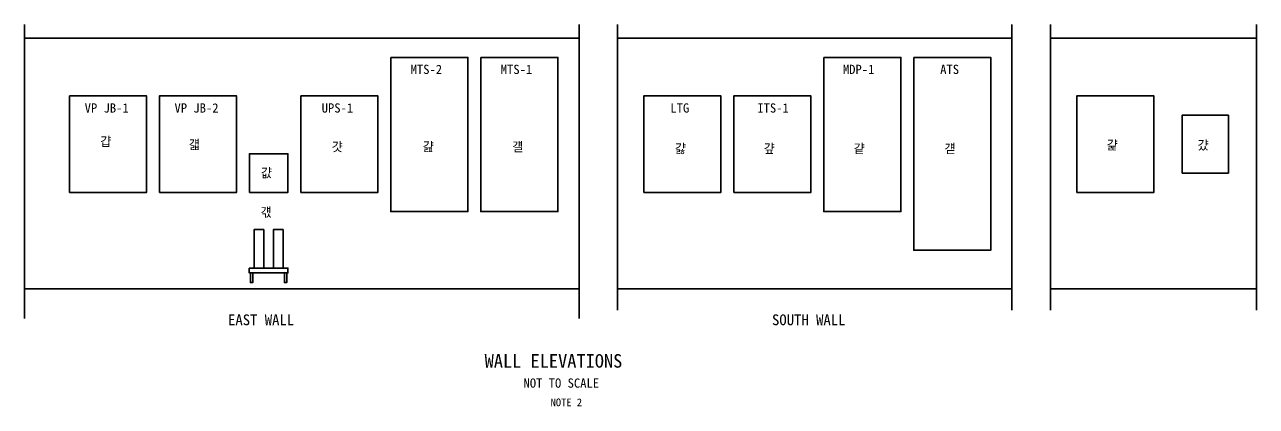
# Model space of a CAD drawing. Extents: x 0 to 31.9, y -2.3 to 7.6.
import ezdxf

# ---------------------------------------------------------------- set-up
doc = ezdxf.new("R2010")
doc.units = 0
doc.layers.add('Sheets_General Details - Sheet Number Text', color=7, linetype='Continuous')
doc.layers.add('Sheets_General Details - Version Text', color=7, linetype='Continuous')

msp = doc.modelspace()

# ---------------------------------------------------------------- linework, layer by layer
at = {"layer": 'Sheets_General Details - Version Text'}
for p, q in [((0, 7.617), (0, 0)), ((14.379, 7.617), (14.379, 0)), ((15.379, 7.617), (15.379, 0.214)), ((25.608, 7.617), (25.608, 0.214)), ((26.608, 7.617), (26.608, 0.214)), ((31.947, 7.617), (31.947, 0.214)), ((14.379, 7.269), (0, 7.269)), ((25.608, 7.269), (15.379, 7.269)), ((31.947, 7.269), (26.608, 7.269)), ((14.379, 0.769), (0, 0.769)), ((25.608, 0.769), (15.379, 0.769)), ((31.947, 0.769), (26.608, 0.769))]:
    msp.add_line(p, q, dxfattribs=at)
for points in [[(9.497, 6.769), (11.497, 6.769), (11.497, 2.769), (9.497, 2.769)], [(11.83, 6.769), (13.83, 6.769), (13.83, 2.769), (11.83, 2.769)], [(20.726, 6.769), (22.726, 6.769), (22.726, 2.769), (20.726, 2.769)], [(23.06, 6.769), (25.06, 6.769), (25.06, 1.769), (23.06, 1.769)], [(1.164, 3.269), (3.164, 3.269), (3.164, 5.769), (1.164, 5.769)], [(3.497, 3.269), (5.497, 3.269), (5.497, 5.769), (3.497, 5.769)], [(7.164, 3.269), (9.164, 3.269), (9.164, 5.769), (7.164, 5.769)], [(16.06, 3.269), (18.06, 3.269), (18.06, 5.769), (16.06, 5.769)], [(18.393, 3.269), (20.393, 3.269), (20.393, 5.769), (18.393, 5.769)], [(27.289, 3.269), (29.289, 3.269), (29.289, 5.769), (27.289, 5.769)], [(30.022, 3.769), (31.222, 3.769), (31.222, 5.269), (30.022, 5.269)], [(5.83, 3.269), (6.83, 3.269), (6.83, 4.269), (5.83, 4.269)], [(6.202, 1.306), (5.952, 1.306), (5.952, 2.306), (6.202, 2.306)], [(6.702, 1.306), (6.452, 1.306), (6.452, 2.306), (6.702, 2.306)], [(5.827, 1.306), (6.827, 1.306), (6.827, 1.181), (5.827, 1.181)], [(5.917, 1.181), (5.857, 1.181), (5.857, 0.931), (5.917, 0.931)], [(6.797, 1.181), (6.737, 1.181), (6.737, 0.931), (6.797, 0.931)]]:
    msp.add_lwpolyline(points, close=True, dxfattribs=at)

# ---------------------------------------------------------------- texts
at = {"layer": 'Sheets_General Details - Sheet Number Text'}
for s, height, p in [('MTS-2', 0.24, (10.011, 6.337)), ('MTS-1', 0.24, (12.348, 6.337)), ('MDP-1', 0.24, (21.223, 6.337)), ('ATS', 0.24, (23.746, 6.337)), ('VP JB-1', 0.24, (1.557, 5.337)), ('VP JB-2', 0.24, (3.887, 5.337)), ('UPS-1', 0.24, (7.704, 5.337)), ('LTG', 0.24, (16.748, 5.337)), ('ITS-1', 0.24, (19.003, 5.337)), ('걉', 0.24, (1.963, 4.466)), ('걟', 0.24, (4.257, 4.388)), ('걋', 0.24, (7.966, 4.333)), ('걆', 0.24, (10.328, 4.333)), ('걜', 0.24, (12.646, 4.333)), ('걇', 0.24, (16.868, 4.283)), ('걒', 0.24, (19.169, 4.285)), ('걑', 0.24, (21.501, 4.283)), ('걛', 0.24, (23.856, 4.283)), ('걅', 0.24, (28.069, 4.376)), ('걌', 0.24, (30.422, 4.374)), ('걊', 0.24, (6.128, 3.656)), ('걗', 0.24, (6.119, 2.636)), ('EAST WALL', 0.28, (5.276, -0.175)), ('SOUTH WALL', 0.28, (19.385, -0.175)), ('WALL ELEVATIONS', 0.35, (11.931, -1.275)), ('NOT TO SCALE', 0.24, (12.94, -1.795)), ('NOTE 2', 0.2, (13.642, -2.275))]:
    msp.add_text(s, height=height, dxfattribs=at).set_placement(p)

doc.saveas('drawing.dxf')
